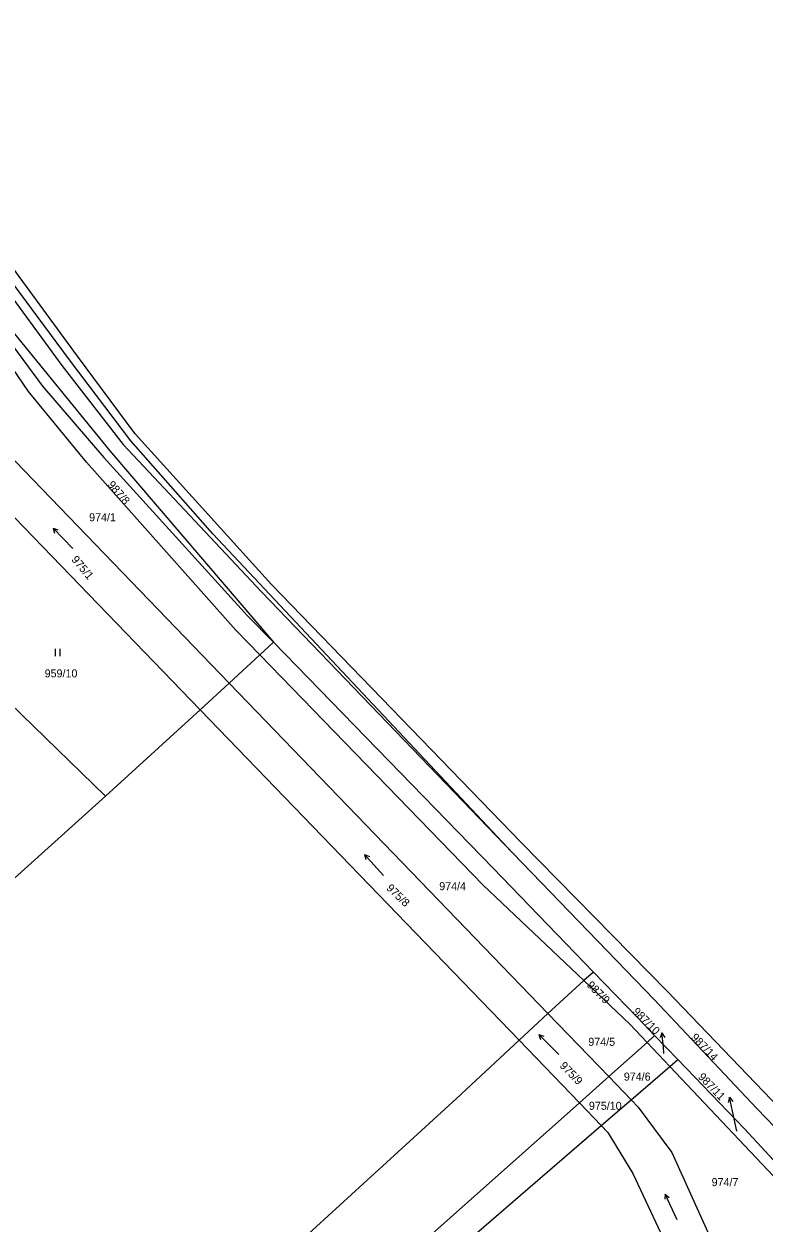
# Model space of a CAD drawing. Extents: x -757266 to -753360, y -1162585 to -1157740.
# Drawn here: x -756464.1 to -756306.9, y -1158051.1 to -1157796.2 of the extents above; entities that cross this region are included whole.
import ezdxf

# ---------------------------------------------------------------- set-up
doc = ezdxf.new("R2010")
doc.units = 0
for name, color, linetype in [('Hranice kat_území', 7, 'Continuous'), ('Hranice parcel', 7, 'Continuous'), ('Parcelní čísla', 7, 'Continuous'), ('Pop  PČ popisy', 7, 'Continuous'), ('Vnitřní kresba', 7, 'Continuous'), ('Značky kultur', 7, 'Continuous')]:
    doc.layers.add(name, color=color, linetype=linetype)

msp = doc.modelspace()

# ---------------------------------------------------------------- linework, layer by layer
at = {"layer": 'Hranice kat_území'}
msp.add_lwpolyline([(-756291.66, -1158038.98), (-756327.49, -1158001.71), (-756358.51, -1157970.13), (-756411.5, -1157915.3), (-756440.51, -1157883.28), (-756452.71, -1157866.81), (-756483.2, -1157825.33)], dxfattribs=at)
at = {"layer": 'Hranice parcel'}
for p, q in [((-756489.22, -1157865.1), (-756420.53, -1157936.28)), ((-756440.51, -1157883.28), (-756452.71, -1157866.81)), ((-756468.05, -1157899.08), (-756426.66, -1157941.95)), ((-756446.78, -1157960.25), (-756491.12, -1157917.32)), ((-756420.53, -1157936.28), (-756414.03, -1157930.26)), ((-756426.66, -1157941.95), (-756420.53, -1157936.28)), ((-756420.53, -1157936.28), (-756352.79, -1158006.47)), ((-756446.78, -1157960.25), (-756426.66, -1157941.95)), ((-756426.66, -1157941.95), (-756358.91, -1158012.13)), ((-756591.22, -1158090.24), (-756446.78, -1157960.25)), ((-756343.14, -1157997.63), (-756345.19, -1157999.44)), ((-756352.79, -1158006.47), (-756345.19, -1157999.44)), ((-756358.91, -1158012.13), (-756352.79, -1158006.47)), ((-756352.79, -1158006.47), (-756339.89, -1158019.84)), ((-756358.91, -1158012.13), (-756346.12, -1158025.38)), ((-756339.89, -1158019.84), (-756331.73, -1158012.58)), ((-756331.73, -1158012.58), (-756330.15, -1158011.1)), ((-756326.92, -1158017.67), (-756331.73, -1158012.58)), ((-756325.23, -1158016.21), (-756330.15, -1158011.1)), ((-756335.14, -1158024.76), (-756326.92, -1158017.67)), ((-756326.92, -1158017.67), (-756325.23, -1158016.21)), ((-756298.57, -1158047.71), (-756326.92, -1158017.67)), ((-756346.12, -1158025.38), (-756339.89, -1158019.84)), ((-756339.89, -1158019.84), (-756335.14, -1158024.76)), ((-756346.12, -1158025.38), (-756341.46, -1158030.21)), ((-756341.46, -1158030.21), (-756335.14, -1158024.76))]:
    msp.add_line(p, q, dxfattribs=at)
for points in [[(-756360.26, -1157972.38), (-756423.98, -1157904.58), (-756441.39, -1157884.82), (-756454.21, -1157867.88), (-756484.39, -1157827.24), (-756507.25, -1157796.25)], [(-756452.71, -1157866.81), (-756483.2, -1157825.33), (-756507.25, -1157796.25)], [(-756472.43, -1157854.4), (-756445.9, -1157886.95), (-756411.13, -1157927.58), (-756414.03, -1157930.26)], [(-756414.03, -1157930.26), (-756419.1, -1157925.03), (-756450.85, -1157889.29), (-756463.14, -1157874.29), (-756475.48, -1157856.35)], [(-756235.28, -1158100.81), (-756263.01, -1158069.46), (-756291.66, -1158038.98), (-756327.49, -1158001.71), (-756358.51, -1157970.13), (-756411.5, -1157915.3), (-756440.51, -1157883.28)], [(-756345.19, -1157999.44), (-756366.59, -1157979.2), (-756414.03, -1157930.26)], [(-756265.89, -1158071.37), (-756292.96, -1158042.65), (-756308.43, -1158026.62), (-756330.22, -1158003.44), (-756360.26, -1157972.38)], [(-756330.15, -1158011.1), (-756333.8, -1158007.31), (-756343.14, -1157997.63)], [(-756331.73, -1158012.58), (-756335.4, -1158008.69), (-756345.19, -1157999.44)], [(-756511.11, -1158151.34), (-756372.25, -1158024.47), (-756358.91, -1158012.13)], [(-756296.92, -1158046.18), (-756311.04, -1158030.95), (-756325.23, -1158016.21)], [(-756599, -1158254.75), (-756522.35, -1158184.78), (-756436.68, -1158105.93), (-756346.12, -1158025.38)], [(-756335.14, -1158024.76), (-756333.62, -1158026.33), (-756326.47, -1158035.95), (-756314.51, -1158062.41)], [(-756594.3, -1158258.74), (-756542.14, -1158210.49), (-756496.19, -1158169.53), (-756473.09, -1158147.67), (-756441.04, -1158117.57), (-756403.79, -1158084.03), (-756341.46, -1158030.21)], [(-756341.46, -1158030.21), (-756340.04, -1158031.68), (-756334.73, -1158040.39), (-756321.46, -1158068.82)]]:
    msp.add_lwpolyline(points, dxfattribs=at)
at = {"layer": 'Pop  PČ popisy'}
for p, q in [((-756328.584, -1158010.565), (-756328.977, -1158011.614)), ((-756328.27, -1158013.55), (-756328.584, -1158010.565)), ((-756328.584, -1158010.565), (-756327.981, -1158011.509)), ((-756328.14, -1158014.91), (-756328.27, -1158013.55)), ((-756314.214, -1158024.225), (-756314.496, -1158025.308)), ((-756313.59, -1158027.16), (-756314.214, -1158024.225)), ((-756314.214, -1158024.225), (-756313.516, -1158025.1)), ((-756312.67, -1158031.41), (-756313.59, -1158027.16))]:
    msp.add_line(p, q, dxfattribs=at)
at = {"layer": 'Vnitřní kresba'}
for p, q in [((-756486.08, -1157827.82), (-756456.07, -1157868.77)), ((-756473.56, -1157855.13), (-756460.17, -1157873.17)), ((-756456.07, -1157868.77), (-756443.07, -1157885.58)), ((-756460.17, -1157873.17), (-756447.17, -1157888.3)), ((-756443.07, -1157885.58), (-756413.65, -1157916.87)), ((-756447.17, -1157888.3), (-756416.59, -1157921.97)), ((-756413.65, -1157916.87), (-756360.26, -1157972.38)), ((-756416.59, -1157921.97), (-756411.13, -1157927.58)), ((-756364.48, -1157975.52), (-756411.13, -1157927.58)), ((-756343.14, -1157997.63), (-756364.48, -1157975.52))]:
    msp.add_line(p, q, dxfattribs=at)
at = {"layer": 'Značky kultur'}
for p, q in [((-756453.762, -1157907.69), (-756457.93, -1157903.374)), ((-756457.93, -1157903.374), (-756457.612, -1157904.425)), ((-756457.93, -1157903.374), (-756456.89, -1157903.728)), ((-756457.431, -1157930.51), (-756457.431, -1157929.01)), ((-756456.43, -1157930.51), (-756456.43, -1157929.01)), ((-756387.748, -1157977.151), (-756391.762, -1157972.692)), ((-756391.762, -1157972.692), (-756391.481, -1157973.754)), ((-756391.762, -1157972.692), (-756390.736, -1157973.083)), ((-756350.485, -1158015.173), (-756354.727, -1158010.931)), ((-756354.727, -1158010.931), (-756354.391, -1158011.976)), ((-756354.727, -1158010.931), (-756353.682, -1158011.267)), ((-756327.897, -1158044.812), (-756327.939, -1158045.909)), ((-756325.362, -1158050.25), (-756327.897, -1158044.812)), ((-756327.897, -1158044.812), (-756327.03, -1158045.486))]:
    msp.add_line(p, q, dxfattribs=at)

# ---------------------------------------------------------------- texts
at = {"layer": 'Parcelní čísla'}
for s, rotation, p in [('987/8', 311, (-756446.471, -1157894.197)), ('975/1', 310, (-756454.141, -1157910.076)), ('975/8', 316, (-756387.25, -1157979.961)), ('987/9', 315, (-756344.661, -1158000.541)), ('987/10', 315, (-756334.941, -1158006.171)), ('987/14', 313.999997, (-756322.531, -1158011.65)), ('975/9', 313.999997, (-756350.411, -1158017.66)), ('987/11', 313.999997, (-756321.021, -1158020.03))]:
    msp.add_text(s, height=1.7, rotation=rotation, dxfattribs=at).set_placement(p)
for s, p in [('974/1', (-756450.27, -1157901.88)), ('959/10', (-756459.72, -1157935.04)), ('974/4', (-756375.89, -1157980.24)), ('974/5', (-756344.22, -1158013.3)), ('974/6', (-756336.67, -1158020.69)), ('975/10', (-756344.09, -1158026.89)), ('974/7', (-756318.02, -1158043.11))]:
    msp.add_text(s, height=1.7, dxfattribs=at).set_placement(p)

doc.saveas('drawing.dxf')
